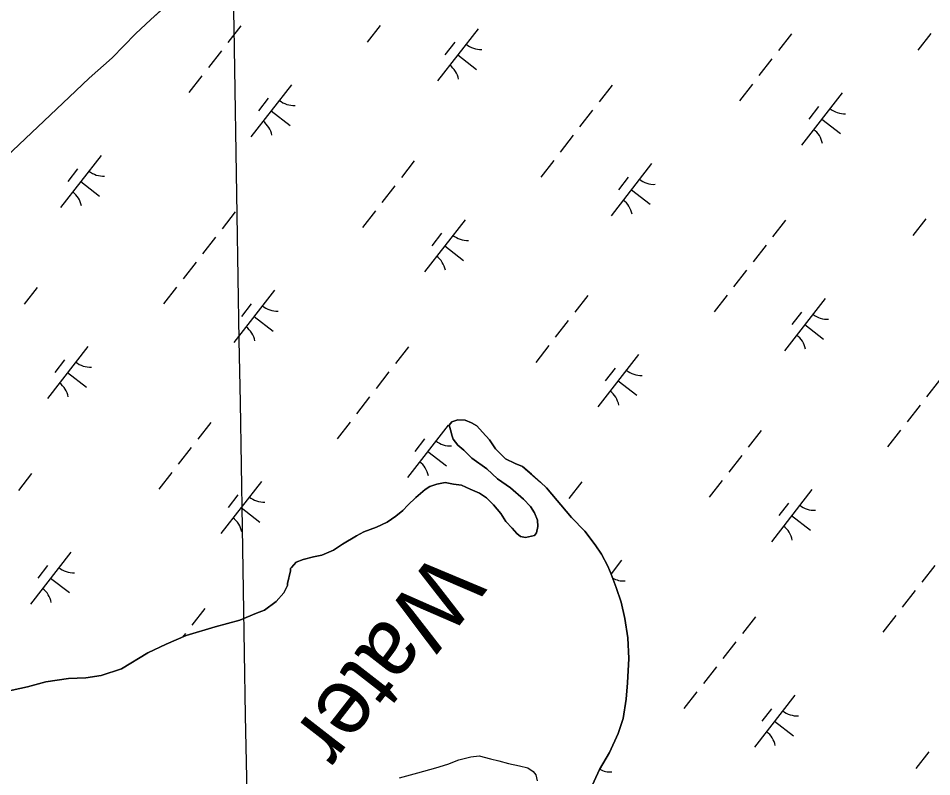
# Model space of a CAD drawing. Extents: x 3888273 to 3909528, y 158682 to 181032.
# Drawn here: x 3898984 to 3899675, y 171905 to 172479 of the extents above; entities that cross this region are included whole.
import ezdxf

# ---------------------------------------------------------------- set-up
doc = ezdxf.new("R2010")
doc.units = 0
for name, color, linetype in [('V-GRID-MAJR', 7, 'Continuous'), ('V-RIVR-IDEN', 7, 'Continuous'), ('V-TOPO-SHOR', 7, 'Continuous'), ('V-WETL-SWMP', 7, 'Continuous')]:
    doc.layers.add(name, color=color, linetype=linetype)

msp = doc.modelspace()

# ---------------------------------------------------------------- linework, layer by layer
at = {"layer": 'V-GRID-MAJR'}
msp.add_spline([(3899339.28, 161091.93), (3899310.23, 162813.43), (3899207.97, 168873.65), (3899105.71, 174933.86), (3899088.15, 175974.62)], degree=3, dxfattribs=at)
at = {"layer": 'V-TOPO-SHOR'}
for points in [[(3898975.09, 172374.13), (3899022.52, 172418.94), (3899037.54, 172433.47), (3899054.95, 172448.82), (3899072.72, 172466.98), (3899084.18, 172477.88), (3899107.91, 172499.28)], [(3899415.68, 171892.51), (3899423.88, 171910.16), (3899431.33, 171923.02), (3899437.97, 171937.46), (3899441.84, 171948.68), (3899444.08, 171963.47), (3899445.15, 171975.86), (3899446.15, 171994.23), (3899445.19, 172009.79), (3899443.04, 172024.54), (3899440.12, 172036.88), (3899436.41, 172048.02), (3899432.71, 172057.96), (3899430.25, 172063.93), (3899425.37, 172073.06), (3899420.5, 172080.19), (3899412.81, 172090.49), (3899402.72, 172100.76), (3899383.72, 172123.32), (3899379.28, 172127.67), (3899372.43, 172133.58), (3899365.58, 172139.5), (3899359.97, 172141.83), (3899352.75, 172145.35), (3899345.08, 172152.86), (3899340.62, 172159.6), (3899335.37, 172165.53), (3899330.93, 172170.27), (3899326.91, 172172.63), (3899322.1, 172174.57), (3899316.51, 172174.91), (3899312.14, 172173.27), (3899310.17, 172170.85), (3899311, 172167.27), (3899312.25, 172162.49)], [(3899312.25, 172162.49), (3899313.07, 172160.11), (3899316.71, 172155.75), (3899321.14, 172151.81), (3899327.19, 172145.88), (3899338.46, 172137.62), (3899346.52, 172130.12), (3899356.57, 172123.44), (3899366.24, 172114.75), (3899371.49, 172109.22), (3899374.73, 172104.46), (3899376.79, 172098.9), (3899377.24, 172094.11), (3899376.09, 172089.31), (3899374.52, 172087.3), (3899367.75, 172085.63), (3899364.15, 172086.39), (3899361.33, 172088.76), (3899357.69, 172092.71), (3899352.85, 172097.85), (3899349.19, 172103.8), (3899343.53, 172110.52), (3899338.29, 172115.66), (3899333.06, 172119.2), (3899325.84, 172122.31), (3899319.43, 172125.44), (3899313.43, 172126.18), (3899307.03, 172127.31), (3899300.66, 172126.04), (3899295.48, 172124.39), (3899291.91, 172121.96), (3899284.79, 172115.9), (3899278.86, 172110.24), (3899274.91, 172106.21), (3899269.77, 172101.77), (3899263.03, 172097.3), (3899255.08, 172093.63), (3899245.54, 172089.93), (3899239.98, 172087.08), (3899229.27, 172080.58), (3899222.53, 172076.12), (3899213.79, 172072.43), (3899207.42, 172071.17), (3899199.45, 172069.09), (3899194.28, 172067.04), (3899190.73, 172063.01), (3899189.94, 172062.21), (3899189.96, 172060.61), (3899187.67, 172051), (3899187.68, 172049.41), (3899184.95, 172043.79), (3899179.03, 172037.34), (3899170.31, 172030.86), (3899164.35, 172028.4), (3899151.63, 172023.08), (3899132.92, 172018.09), (3899111.03, 172011.48), (3899095.93, 172004.93), (3899082.03, 171998.39), (3899062.19, 171986.21), (3899046.68, 171981.26), (3899035.12, 171979.54), (3899021.95, 171979), (3899004.81, 171976.43), (3898990.88, 171972.69), (3898971.36, 171968.49)], [(3899272.44, 171903.93), (3899286.36, 171907.67), (3899299.87, 171911.4), (3899309.02, 171914.28), (3899317.35, 171917.56), (3899326.5, 171919.65), (3899332.87, 171920.52), (3899341.27, 171918.21), (3899347.67, 171916.68), (3899354.87, 171914.77), (3899363.26, 171912.86), (3899369.66, 171911.33), (3899373.67, 171908.58), (3899375.69, 171906.21), (3899376.54, 171901.43)]]:
    msp.add_lwpolyline(points, dxfattribs=at)
at = {"layer": 'V-WETL-SWMP'}
for p, q in [((3899107.91, 172499.28), (3899084.18, 172477.87)), ((3899084.18, 172477.87), (3899072.72, 172466.98)), ((3899152.41, 172473.13), (3899142.59, 172460.5)), ((3899257.87, 172473.37), (3899248.05, 172460.75)), ((3899332.02, 172470.9), (3899301.31, 172431.44)), ((3899072.72, 172466.98), (3899054.95, 172448.82)), ((3899569.08, 172466.91), (3899559.25, 172454.28)), ((3899674.54, 172467.15), (3899664.72, 172454.52)), ((3899314.26, 172460.64), (3899306.89, 172451.17)), ((3899137.67, 172454.19), (3899127.85, 172441.56)), ((3899316.66, 172451.17), (3899330.87, 172440.12)), ((3899054.95, 172448.82), (3899037.54, 172433.47)), ((3899554.34, 172447.96), (3899544.51, 172435.34)), ((3899037.54, 172433.47), (3899022.52, 172418.94)), ((3899122.93, 172435.25), (3899113.11, 172422.62)), ((3899539.6, 172429.02), (3899529.78, 172416.39)), ((3899190.78, 172428.45), (3899160.07, 172388.99)), ((3899433.37, 172428.05), (3899423.54, 172415.43)), ((3899607.44, 172422.23), (3899576.74, 172382.76)), ((3899022.52, 172418.94), (3898975.09, 172374.13)), ((3899173.02, 172418.19), (3899165.65, 172408.72)), ((3899175.42, 172408.72), (3899189.63, 172397.67)), ((3899418.63, 172409.11), (3899408.8, 172396.48)), ((3899589.69, 172411.97), (3899582.32, 172402.5)), ((3899592.09, 172402.49), (3899606.3, 172391.44)), ((3899403.89, 172390.17), (3899394.07, 172377.54)), ((3899046.63, 172374.98), (3899015.93, 172335.52)), ((3899283.69, 172370.99), (3899273.87, 172358.36)), ((3899389.15, 172371.23), (3899379.33, 172358.6)), ((3899463.3, 172368.76), (3899432.59, 172329.29)), ((3899028.87, 172364.72), (3899021.5, 172355.25)), ((3899031.28, 172355.25), (3899045.48, 172344.2)), ((3899445.54, 172358.5), (3899438.17, 172349.03)), ((3899268.95, 172352.04), (3899259.13, 172339.42)), ((3899447.95, 172349.02), (3899462.15, 172337.97)), ((3899147.98, 172332.14), (3899138.16, 172319.51)), ((3899254.22, 172333.1), (3899244.39, 172320.47)), ((3899322.06, 172326.31), (3899291.35, 172286.84)), ((3899564.65, 172325.91), (3899554.82, 172313.28)), ((3899670.88, 172326.88), (3899661.06, 172314.25)), ((3899133.24, 172313.19), (3899123.42, 172300.57)), ((3899304.3, 172316.05), (3899296.93, 172306.58)), ((3899306.7, 172306.58), (3899320.91, 172295.52)), ((3899549.91, 172306.97), (3899540.09, 172294.34)), ((3899118.51, 172294.25), (3899108.68, 172281.62)), ((3899535.17, 172288.03), (3899525.35, 172275.4)), ((3898998.3, 172275.07), (3898988.48, 172262.44)), ((3899103.77, 172275.31), (3899093.94, 172262.68)), ((3899177.91, 172272.84), (3899147.21, 172233.37)), ((3899414.97, 172268.84), (3899405.15, 172256.21)), ((3899520.43, 172269.08), (3899510.61, 172256.46)), ((3899594.58, 172266.61), (3899563.87, 172227.15)), ((3899160.15, 172262.58), (3899152.78, 172253.11)), ((3899576.82, 172256.35), (3899569.45, 172246.88)), ((3899162.56, 172253.11), (3899176.76, 172242.05)), ((3899400.23, 172249.9), (3899390.41, 172237.27)), ((3899579.23, 172246.88), (3899593.43, 172235.83)), ((3899036.67, 172230.39), (3899005.97, 172190.93)), ((3899279.26, 172229.99), (3899269.44, 172217.36)), ((3899385.5, 172230.96), (3899375.67, 172218.33)), ((3899453.34, 172224.16), (3899422.63, 172184.7)), ((3899018.91, 172220.13), (3899011.54, 172210.66)), ((3899021.32, 172210.66), (3899035.52, 172199.6)), ((3899264.52, 172211.05), (3899254.7, 172198.42)), ((3899435.58, 172213.9), (3899428.21, 172204.43)), ((3899437.98, 172204.43), (3899452.19, 172193.38)), ((3899681.19, 172204.82), (3899671.37, 172192.19)), ((3899249.79, 172192.11), (3899239.96, 172179.48)), ((3899666.45, 172185.88), (3899656.63, 172173.25)), ((3899235.05, 172173.17), (3899225.22, 172160.54)), ((3899310.17, 172170.85), (3899312.14, 172173.27)), ((3899312.14, 172173.27), (3899316.51, 172174.91)), ((3899316.51, 172174.91), (3899322.1, 172174.57)), ((3899322.1, 172174.57), (3899326.91, 172172.63)), ((3899129.59, 172172.92), (3899119.76, 172160.29)), ((3899309.19, 172170.69), (3899278.49, 172131.23)), ((3899311, 172167.27), (3899310.17, 172170.85)), ((3899312.25, 172162.49), (3899311, 172167.27)), ((3899326.91, 172172.63), (3899330.93, 172170.27)), ((3899330.93, 172170.27), (3899335.37, 172165.53)), ((3899546.25, 172166.7), (3899536.43, 172154.07)), ((3899651.72, 172166.94), (3899641.89, 172154.31)), ((3899291.43, 172160.43), (3899284.07, 172150.96)), ((3899313.07, 172160.11), (3899312.25, 172162.49)), ((3899316.71, 172155.75), (3899313.07, 172160.11)), ((3899335.37, 172165.53), (3899340.62, 172159.6)), ((3899340.62, 172159.6), (3899345.08, 172152.86)), ((3899114.85, 172153.98), (3899105.02, 172141.35)), ((3899321.14, 172151.81), (3899316.71, 172155.75)), ((3899345.08, 172152.86), (3899352.75, 172145.35)), ((3899293.84, 172150.96), (3899308.05, 172139.91)), ((3899327.19, 172145.88), (3899321.14, 172151.81)), ((3899338.46, 172137.62), (3899327.19, 172145.88)), ((3899531.51, 172147.76), (3899521.69, 172135.13)), ((3899352.75, 172145.35), (3899359.97, 172141.83)), ((3899359.97, 172141.83), (3899365.58, 172139.5)), ((3899365.58, 172139.5), (3899379.28, 172127.67)), ((3898993.87, 172134.07), (3898984.05, 172121.44)), ((3899100.11, 172135.04), (3899090.28, 172122.41)), ((3899346.52, 172130.12), (3899338.46, 172137.62)), ((3899167.95, 172128.24), (3899137.25, 172088.78)), ((3899295.48, 172124.39), (3899300.65, 172126.04)), ((3899300.65, 172126.04), (3899307.03, 172127.31)), ((3899307.03, 172127.31), (3899313.43, 172126.18)), ((3899313.43, 172126.18), (3899319.42, 172125.44)), ((3899319.42, 172125.44), (3899325.84, 172122.31)), ((3899356.57, 172123.44), (3899346.52, 172130.12)), ((3899379.28, 172127.67), (3899383.72, 172123.32)), ((3899410.54, 172127.85), (3899400.72, 172115.22)), ((3899516.78, 172128.81), (3899506.95, 172116.19)), ((3899150.19, 172117.99), (3899142.82, 172108.51)), ((3899284.79, 172115.9), (3899291.91, 172121.96)), ((3899291.91, 172121.96), (3899295.48, 172124.39)), ((3899325.84, 172122.31), (3899333.06, 172119.2)), ((3899333.06, 172119.2), (3899338.29, 172115.66)), ((3899366.24, 172114.75), (3899356.57, 172123.44)), ((3899383.72, 172123.32), (3899402.72, 172100.77)), ((3899584.62, 172122.02), (3899553.91, 172082.56)), ((3899278.86, 172110.24), (3899284.79, 172115.9)), ((3899338.29, 172115.66), (3899343.53, 172110.52)), ((3899371.49, 172109.22), (3899366.24, 172114.75)), ((3899566.86, 172111.76), (3899559.49, 172102.29)), ((3899152.6, 172108.51), (3899166.8, 172097.46)), ((3899269.77, 172101.77), (3899274.91, 172106.21)), ((3899274.91, 172106.21), (3899278.86, 172110.24)), ((3899343.53, 172110.52), (3899349.19, 172103.8)), ((3899374.73, 172104.46), (3899371.49, 172109.22)), ((3899376.79, 172098.9), (3899374.73, 172104.46)), ((3899255.08, 172093.63), (3899263.03, 172097.3)), ((3899263.03, 172097.3), (3899269.77, 172101.77)), ((3899349.19, 172103.8), (3899352.85, 172097.85)), ((3899352.85, 172097.85), (3899357.69, 172092.71)), ((3899377.24, 172094.11), (3899376.79, 172098.9)), ((3899402.72, 172100.77), (3899412.81, 172090.49)), ((3899569.27, 172102.29), (3899583.47, 172091.23)), ((3899245.54, 172089.93), (3899255.08, 172093.63)), ((3899357.69, 172092.71), (3899361.33, 172088.75)), ((3899376.09, 172089.31), (3899377.24, 172094.11)), ((3899412.81, 172090.49), (3899420.5, 172080.19)), ((3899229.27, 172080.58), (3899239.98, 172087.08)), ((3899239.98, 172087.08), (3899245.54, 172089.93)), ((3899361.33, 172088.75), (3899364.15, 172086.39)), ((3899364.15, 172086.39), (3899367.75, 172085.63)), ((3899367.75, 172085.63), (3899374.52, 172087.3)), ((3899374.52, 172087.3), (3899376.09, 172089.31)), ((3899222.53, 172076.12), (3899229.27, 172080.58)), ((3899420.5, 172080.19), (3899425.37, 172073.06)), ((3899023.8, 172074.77), (3898993.1, 172035.31)), ((3899199.45, 172069.09), (3899207.42, 172071.17)), ((3899207.42, 172071.17), (3899213.79, 172072.43)), ((3899213.79, 172072.43), (3899222.53, 172076.12)), ((3899425.37, 172073.06), (3899430.25, 172063.93)), ((3899006.05, 172064.52), (3898998.68, 172055.04)), ((3899189.94, 172062.21), (3899190.73, 172063.01)), ((3899190.73, 172063.01), (3899194.28, 172067.04)), ((3899194.28, 172067.04), (3899199.45, 172069.09)), ((3899430.25, 172063.93), (3899432.71, 172057.96)), ((3899440.47, 172068.55), (3899432.55, 172058.36)), ((3899677.53, 172064.55), (3899667.71, 172051.92)), ((3899187.67, 172051), (3899189.96, 172060.61)), ((3899189.96, 172060.61), (3899189.94, 172062.21)), ((3899432.71, 172057.96), (3899436.41, 172048.02)), ((3899008.45, 172055.04), (3899022.66, 172043.99)), ((3899184.95, 172043.79), (3899187.68, 172049.41)), ((3899187.68, 172049.41), (3899187.67, 172051)), ((3899179.03, 172037.34), (3899184.95, 172043.79)), ((3899436.41, 172048.02), (3899440.12, 172036.88)), ((3899662.8, 172045.61), (3899652.97, 172032.98)), ((3899170.31, 172030.86), (3899179.03, 172037.34)), ((3899440.12, 172036.88), (3899443.04, 172024.54)), ((3899125.16, 172031.93), (3899115.33, 172019.3)), ((3899151.63, 172023.08), (3899164.35, 172028.4)), ((3899164.35, 172028.4), (3899170.31, 172030.86)), ((3899132.92, 172018.09), (3899151.63, 172023.08)), ((3899443.04, 172024.54), (3899445.19, 172009.79)), ((3899541.82, 172025.7), (3899532, 172013.07)), ((3899648.06, 172026.67), (3899638.23, 172014.04)), ((3899111.03, 172011.48), (3899132.92, 172018.09)), ((3899095.93, 172004.93), (3899111.03, 172011.48)), ((3899110.42, 172012.99), (3899108.33, 172010.3)), ((3899445.19, 172009.79), (3899446.15, 171994.23)), ((3899082.03, 171998.4), (3899095.93, 172004.93)), ((3899527.09, 172006.76), (3899517.26, 171994.13)), ((3899062.19, 171986.21), (3899082.03, 171998.4)), ((3899446.15, 171994.23), (3899445.15, 171975.86)), ((3899512.35, 171987.82), (3899502.52, 171975.19)), ((3899021.95, 171979), (3899035.12, 171979.54)), ((3899035.12, 171979.54), (3899046.68, 171981.26)), ((3899046.68, 171981.26), (3899062.19, 171986.21)), ((3898971.36, 171968.49), (3898990.88, 171972.69)), ((3898990.88, 171972.69), (3899004.81, 171976.43)), ((3899004.81, 171976.43), (3899021.95, 171979)), ((3899445.15, 171975.86), (3899444.08, 171963.47)), ((3899497.61, 171968.88), (3899487.78, 171956.25)), ((3899571.75, 171966.4), (3899541.05, 171926.94)), ((3899444.08, 171963.47), (3899441.84, 171948.68)), ((3899554, 171956.14), (3899546.63, 171946.67)), ((3899441.84, 171948.68), (3899437.97, 171937.46)), ((3899556.4, 171946.67), (3899570.61, 171935.62)), ((3899437.97, 171937.46), (3899431.33, 171923.02)), ((3899431.33, 171923.02), (3899423.88, 171910.16)), ((3899673.1, 171923.56), (3899663.28, 171910.93)), ((3899423.88, 171910.16), (3899415.68, 171892.51))]:
    msp.add_line(p, q, dxfattribs=at)
msp.add_lwpolyline([(3899272.44, 171903.93), (3899286.36, 171907.67), (3899299.88, 171911.4), (3899309.02, 171914.28), (3899317.35, 171917.56), (3899326.5, 171919.65), (3899332.87, 171920.52), (3899341.27, 171918.21), (3899347.67, 171916.68), (3899354.87, 171914.77), (3899363.26, 171912.86), (3899369.66, 171911.33), (3899373.67, 171908.58), (3899375.69, 171906.21), (3899376.54, 171901.43)], dxfattribs=at)
for centre, start, end in [((3899333.81, 172472.82), 231.34298, 272.88664), ((3899299.89, 172429.22), 11.34298, 52.88663), ((3899192.57, 172430.37), 231.34298, 272.88664), ((3899609.24, 172424.15), 231.34298, 272.88664), ((3899158.65, 172386.77), 11.34298, 52.88663), ((3899575.32, 172380.55), 11.34298, 52.88663), ((3899048.43, 172376.9), 231.34298, 272.88664), ((3899465.09, 172370.68), 231.34298, 272.88664), ((3899014.5, 172333.3), 11.34298, 52.88663), ((3899431.17, 172327.08), 11.34298, 52.88663), ((3899323.85, 172328.23), 231.34298, 272.88664), ((3899289.93, 172284.63), 11.34298, 52.88663), ((3899179.71, 172274.76), 231.34298, 272.88664), ((3899596.37, 172268.53), 231.34298, 272.88664), ((3899145.78, 172231.16), 11.34298, 52.88663), ((3899562.45, 172224.93), 11.34298, 52.88663), ((3899038.47, 172232.31), 231.34298, 272.88664), ((3899455.13, 172226.09), 231.34298, 272.88664), ((3899004.54, 172188.71), 11.34298, 52.88663), ((3899421.21, 172182.49), 11.34298, 52.88663), ((3899310.99, 172172.62), 231.34298, 272.88664), ((3899277.06, 172129.02), 11.34298, 52.88663), ((3899169.75, 172130.17), 231.34298, 272.88664), ((3899586.41, 172123.94), 231.34298, 272.88664), ((3899135.82, 172086.57), 11.34298, 52.88663), ((3899552.49, 172080.34), 11.34298, 52.88663), ((3899025.6, 172076.7), 231.34298, 272.88664), ((3899442.27, 172070.47), 241.31054, 272.88664), ((3898991.68, 172033.1), 11.34298, 52.88663), ((3899573.55, 171968.33), 231.34298, 272.88664), ((3899539.63, 171924.73), 11.34298, 52.88663), ((3899432.31, 171925.88), 241.81614, 272.88664)]:
    msp.add_arc(centre, 17.62, start, end, dxfattribs=at)

# ---------------------------------------------------------------- texts
at = {"layer": 'V-RIVR-IDEN'}
msp.add_text('Water', height=50, rotation=232.11852, dxfattribs=at).set_placement((3899299.8, 172077.22))

doc.saveas('drawing.dxf')
